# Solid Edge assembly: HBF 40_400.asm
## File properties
Title: Zylinder
Author: ahadarics
Template: iso assembly.asm
Last saved by: ahadarics
Revision: 44
Application: Solid Edge
Username: ahadarics
Dokumentum tartalom típus: 1
Document Number: HBF 40/400
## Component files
Kit.par
Profilrohr 40_400.par
Mutter.par
Kolbenstange_1_40_400.par
Kolbenstange_2_40_400.par
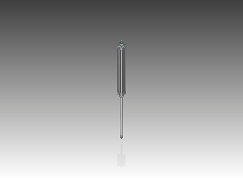
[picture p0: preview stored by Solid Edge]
